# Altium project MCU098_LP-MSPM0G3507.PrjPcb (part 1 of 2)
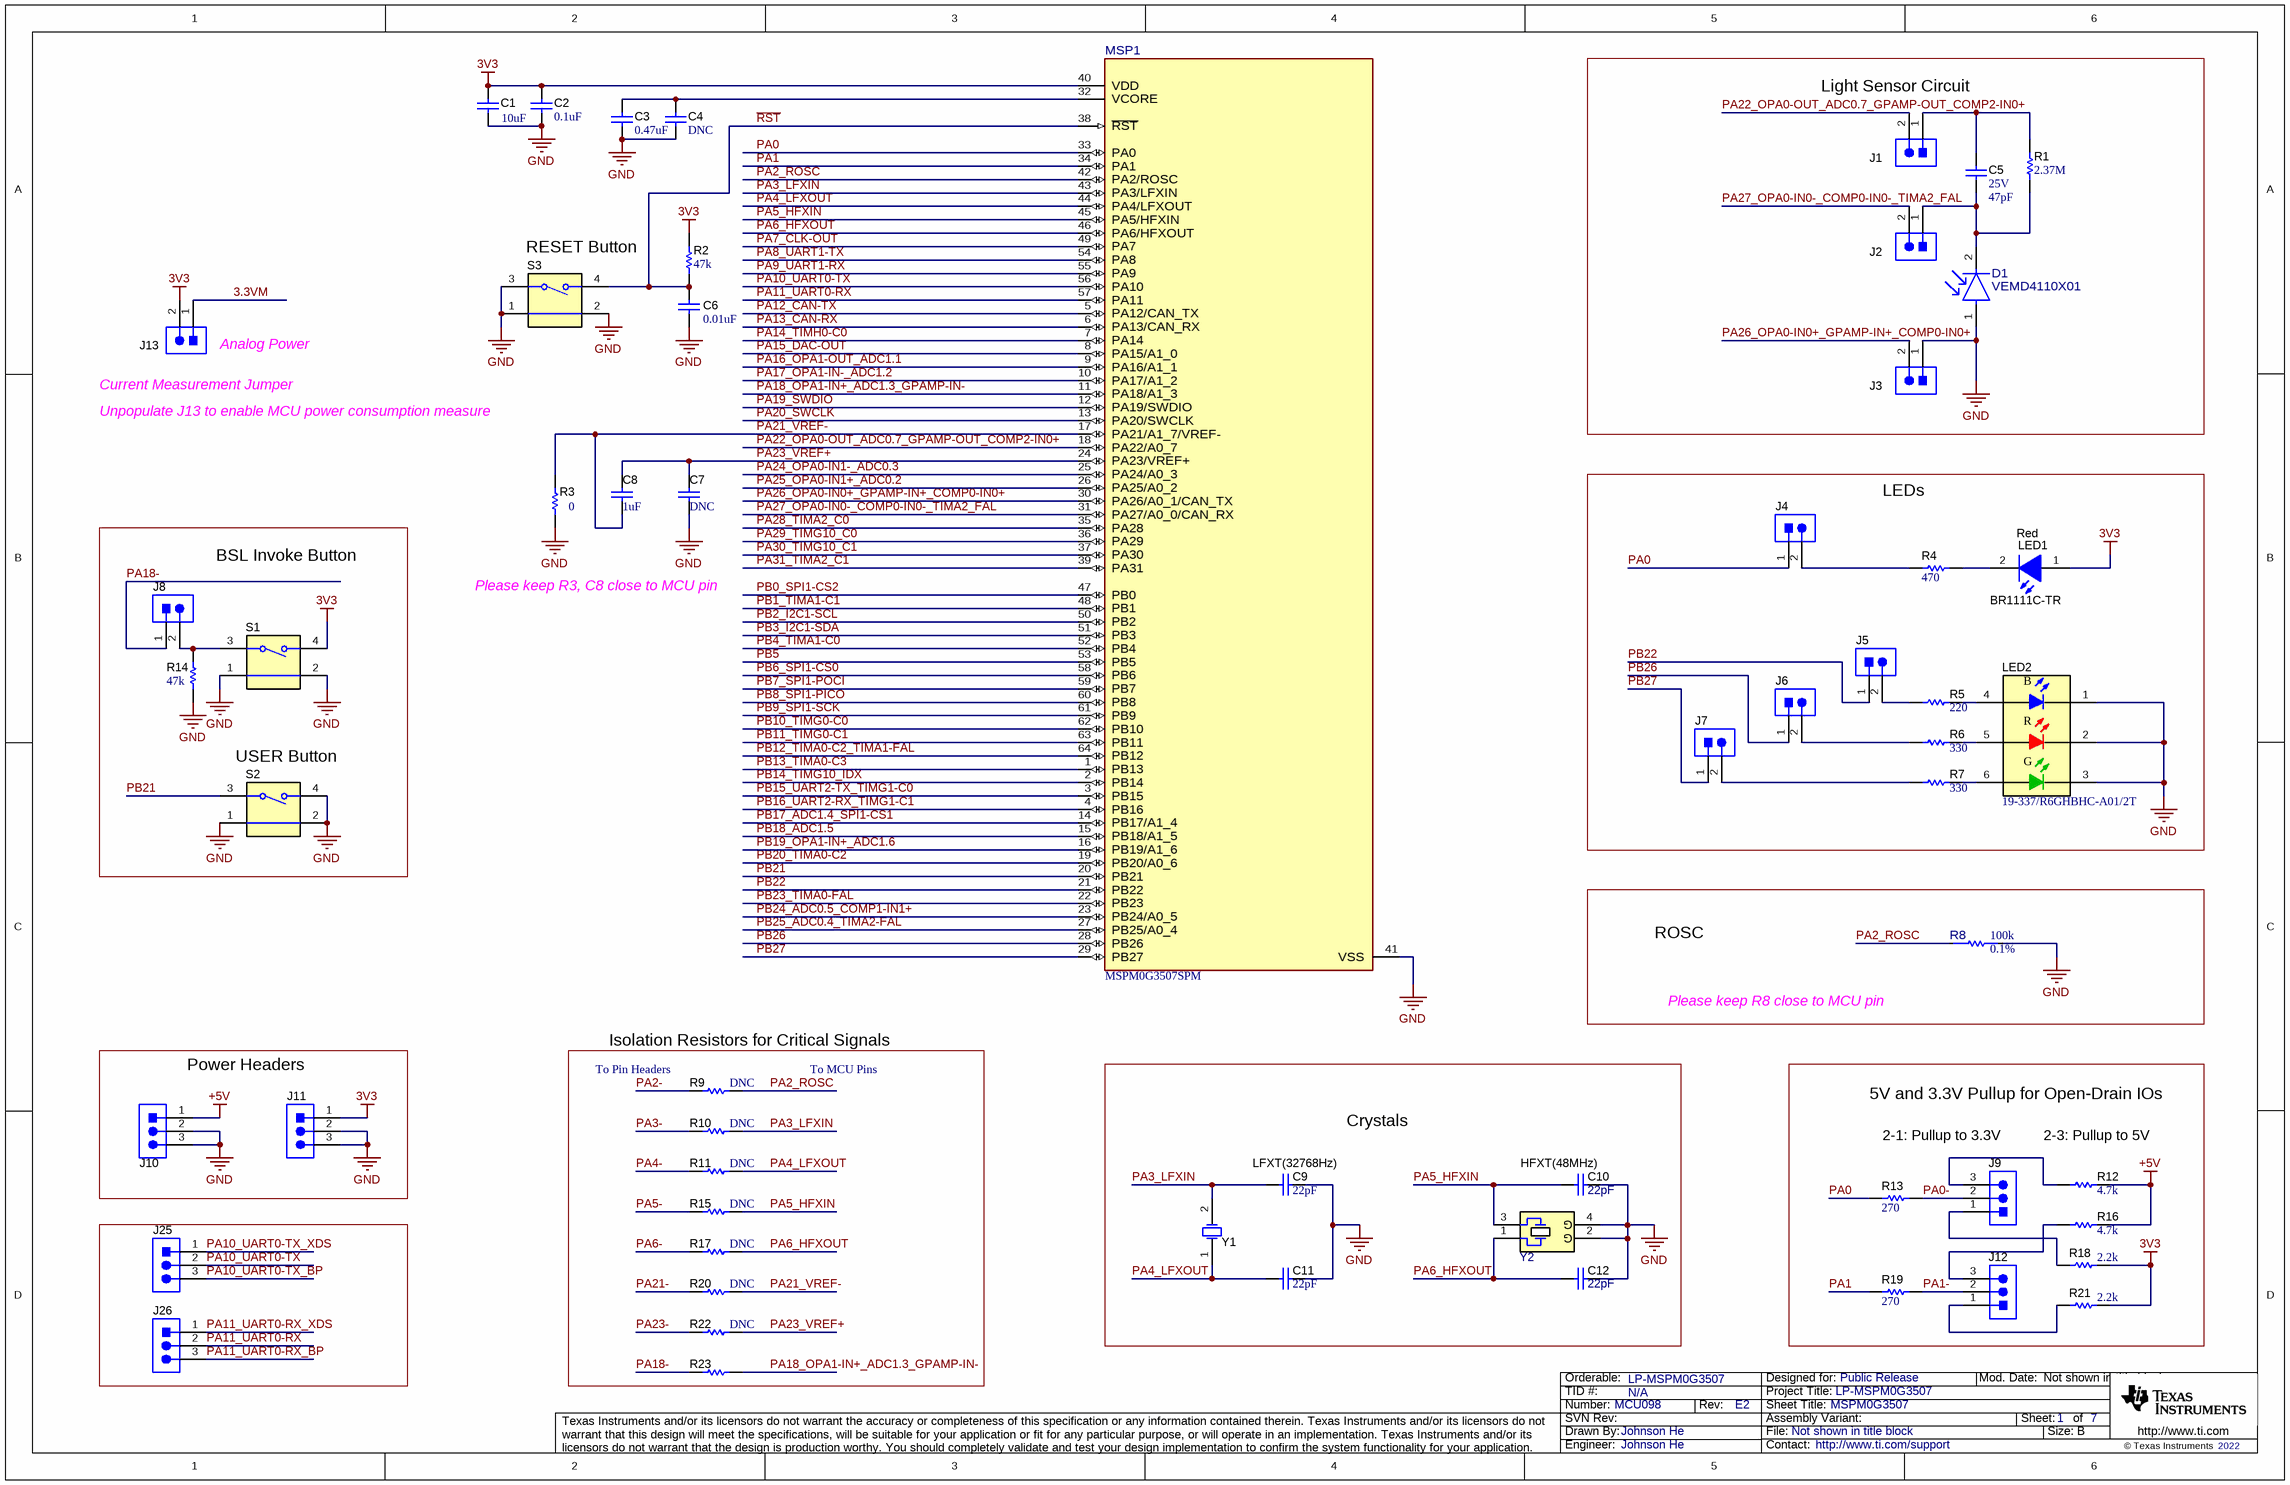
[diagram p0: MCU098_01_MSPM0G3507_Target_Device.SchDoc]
CopyrightYear: 2022; EVM_orderable: LP-MSPM0G3507; PCB_Layout: Johnson He; PCB_Rev: E2; PRJ_Customer: Public Release; PRJ_Engineer: Johnson He; PRJ_Number: MCU098; PRJ_Title: LP-MSPM0G3507; SCH_Rev: E2; TechSupport: http://www.ti.com/support; TID: N/A
7 sheets, 263 parts. Net scope: global (net labels, ports and power ports of the same name join across sheets).
Board file: MCU098_MSPM0G3507_PCB.PcbDoc
Sheets:
  MCU098_01_MSPM0G3507_Target_Device.SchDoc
  MCU098_02_BoosterPack_Connectors.SchDoc
  MCU098_03_XDS110_Debug_Probe.SchDoc
  MCU098_04_XDS110-ET_EnergyTrace.SchDoc
  MCU098_05_XDS110_Target_Interface.SchDoc
  MCU098_06_XDS110-ET_USB_Power.SchDoc
  MCU098_07_Hardware.SchDoc

## Sheet MCU098_01_MSPM0G3507_Target_Device.SchDoc: MSPM0G3507
size 431 x 279 mm; Date: Not shown in title block; ApprovedBy: Not shown in title block; CheckedBy: Not shown in title block; Author: Not shown in title block; CompanyName: Not shown in title block; DrawnBy: Johnson He; Engineer: Not shown in title block; Organization: Not shown in title block; Address1: Not shown in title block; Address2: Not shown in title block; Address3: Not shown in title block; Address4: Not shown in title block; DocumentNumber: 1; Revision: Use project parameter SCH_Rev; SheetNumber: 1; SheetTotal: 7; PageSetup: Record=PageOptions¦CenterHorizontal=True¦CenterVertical=True¦PrintScale=1.00¦XCorrection=1.00¦YCorrection=1.00¦PrintKind=0¦BorderSize=5000000¦LeftOffset=0¦BottomOffset=0¦Orientation=2¦PaperLength=1000¦PaperWidth=1000¦Scale=100¦PaperSource=15¦PrintQuality=600¦MediaType=1¦DitherType=10¦PaperKind=Letter¦PrintScaleMode=1

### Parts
C1  ValueDisplayed: 10uF  [0603]  (hidden comment: GRM188R60J106ME84)
C2  ValueDisplayed: 0.1uF  [0402]  (hidden comment: GRM155R61H104ME14D)
C3  ValueDisplayed: 0.47uF  [0402]  (hidden comment: GRM155R60J474KE19D)
C4  ValueDisplayed: DNC  [0402]  (hidden comment: GRM155R61H104ME14D)  (no BOM)
C5  VDC_V: 25V  ValueDisplayed: 47pF  [0402]  (hidden comment: GRM1555C1E470JA01D)
C6  ValueDisplayed: 0.01uF  [0402]  (hidden comment: GRM155R61C103KA01D)
C7  ValueDisplayed: DNC  [0603]  (hidden comment: C1608X5R1E105K080AC)  (no BOM)
C8  value 1uF  [0603]  (hidden comment: C1608X5R1E105K080AC)
C9  ValueDisplayed: 22pF  [0402]  (hidden comment: GRM1555C1H220JA01D)
C10  ValueDisplayed: 22pF  [0402]  (hidden comment: GRM1555C1H220JA01D)
C11  ValueDisplayed: 22pF  [0402]  (hidden comment: GRM1555C1H220JA01D)
C12  ValueDisplayed: 22pF  [0402]  (hidden comment: GRM1555C1H220JA01D)
D1  VEMD4110X01  [FP-VEMD4110X01_0805-MFG]
J1  90120-0122  [CONN_90120-0122]  (value not drawn)
J2  90120-0122  [CONN_90120-0122]  (value not drawn)
J3  90120-0122  [CONN_90120-0122]  (value not drawn)
J4  90120-0122  [CONN_90120-0122]  (value not drawn)
J5  90120-0122  [CONN_90120-0122]  (value not drawn)
J6  90120-0122  [CONN_90120-0122]  (value not drawn)
J7  90120-0122  [CONN_90120-0122]  (value not drawn)
J8  90120-0122  [CONN_90120-0122]  (value not drawn)
J9  PEC03SAAN  [CONN_PEC03SAAN]  (value not drawn)
J10  PEC03SAAN  [PEC03SAAN_Launchpad_5V0]  (value not drawn)
J11  PEC03SAAN  [PEC03SAAN_Launchpad_3V3]  (value not drawn)
J12  PEC03SAAN  [CONN_PEC03SAAN]  (value not drawn)
J13  90120-0122  [CONN_90120-0122]  (value not drawn)
J25  PEC03SAAN  [CONN_PEC03SAAN]  (value not drawn)
J26  PEC03SAAN  [CONN_PEC03SAAN]  (value not drawn)
LED1  BR1111C-TR  value Red  [1111C_Red]
LED2  19-337/R6GHBHC-A01/2T  [19-337_RGB]
MSP1  MSPM0G3507SPM  [PM0064A-MFG]
R1  ValueDisplayed: 2.37M  [0603]  (hidden comment: CRCW06032M37FKEA)
R2  ValueDisplayed: 47k  [0402]  (hidden comment: CRCW040247K0JNED)
R3  value 0  [0603]  (hidden comment: RC0603JR-070RL)
R4  ValueDisplayed: 470  [0402]  (hidden comment: CRCW0402470RJNED)
R5  ValueDisplayed: 220  [0402]  (hidden comment: CRCW0402220RJNED)
R6  ValueDisplayed: 330  [0402]  (hidden comment: CRCW0402330RJNED)
R7  ValueDisplayed: 330  [0402]  (hidden comment: CRCW0402330RJNED)
R8  Tolerance_%: 0.1%  Res_ohm: 100k  [FP-ERA-2AEB104X_0402-MFG]  (hidden comment: ERA-2AEB104X)
R9  ValueDisplayed: DNC  [0402]  (hidden comment: RC0402JR-070RL)  (no BOM)
R10  ValueDisplayed: DNC  [0402]  (hidden comment: RC0402JR-070RL)  (no BOM)
R11  ValueDisplayed: DNC  [0402]  (hidden comment: RC0402JR-070RL)  (no BOM)
R12  ValueDisplayed: 4.7k  [0603]  (hidden comment: RC0603JR-074K7L)
R13  ValueDisplayed: 270  [0402]  (hidden comment: CRCW0402270RJNED)
R14  ValueDisplayed: 47k  [0402]  (hidden comment: CRCW040247K0JNED)
R15  ValueDisplayed: DNC  [0402]  (hidden comment: RC0402JR-070RL)  (no BOM)
R16  ValueDisplayed: 4.7k  [0603]  (hidden comment: RC0603JR-074K7L)
R17  ValueDisplayed: DNC  [0402]  (hidden comment: RC0402JR-070RL)  (no BOM)
R18  ValueDisplayed: 2.2k  [0603]  (hidden comment: RC0603JR-0710KL)
R19  ValueDisplayed: 270  [0402]  (hidden comment: CRCW0402270RJNED)
R20  ValueDisplayed: DNC  [0402]  (hidden comment: RC0402JR-070RL)  (no BOM)
R21  ValueDisplayed: 2.2k  [0603]  (hidden comment: RC0603JR-0710KL)
R22  ValueDisplayed: DNC  [0402]  (hidden comment: RC0402JR-070RL)  (no BOM)
R23  RC0402JR-070RL  [0402]  (value not drawn)
S1  1188E-1K2-V-TR  [SW_1188E]  (value not drawn)
S2  1188E-1K2-V-TR  [SW_1188E]  (value not drawn)
S3  1188E-1K2-V-TR  [SW_1188E]  (value not drawn)
Y1  X1A0001410014  [Epson_FC-135]  (value not drawn)
Y2  FA-238 48.0000MB-W0  [Epson_FA-238]  (value not drawn)

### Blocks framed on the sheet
Light Sensor Circuit: C5 D1 J1-J3 R1
LEDs: J4-J7 LED1 LED2 R4-R7
ROSC: R8
Power Headers: J10 J11
Isolation Resistors for Critical Signals: R9-R11 R15 R17 R20 R22 R23
Crystals: C9-C12 Y1 Y2
5V and 3.3V Pullup for Open-Drain IOs: J9 J12 R12 R13 R16 R18 R19 R21

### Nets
3V3: C1.1 C2.1 J11.1 J13.2 LED1.1(A) MSP1.40(VDD) R2.2 R18.2 R21.2 S1.4
+5V: J10.1 R12.2 R16.2
GND: C1.2 C2.2 C3.2 C4.2 C6.2 C7.2 C9.1 C10.1 C11.1 C12.1 D1.1(ANODE) J3.1 J10.2 J10.3 J11.2 J11.3 LED2.1(K) LED2.2(K) LED2.3(K) MSP1.41(VSS) R3.1 R8.2 R14.1 S1.1 S1.2 S2.1 S2.2 S2.4 S3.1 S3.2 S3.3 Y2.2(GND) Y2.4(GND)
3.3VM: J13.1
PA0: J4.1 MSP1.33(PA0) R13.1
PA0-: J9.2 R13.2
PA1: MSP1.34(PA1) R19.1
PA1-: J12.2 R19.2
PA2-: R9.1
PA2_ROSC: MSP1.42(PA2/ROSC) R8.1 R9.2
PA3-: R10.1
PA3_LFXIN: C9.2 MSP1.43(PA3/LFXIN) R10.2 Y1.2(OSC2)
PA4-: R11.1
PA4_LFXOUT: C11.2 MSP1.44(PA4/LFXOUT) R11.2 Y1.1(OSC1)
PA5-: R15.1
PA5_HFXIN: C10.2 MSP1.45(PA5/HFXIN) R15.2 Y2.3
PA6-: R17.1
PA6_HFXOUT: C12.2 MSP1.46(PA6/HFXOUT) R17.2 Y2.1
PA7_CLK-OUT: MSP1.49(PA7)
PA8_UART1-TX: MSP1.54(PA8)
PA9_UART1-RX: MSP1.55(PA9)
PA10_UART0-TX: J25.2 MSP1.56(PA10)
PA10_UART0-TX_BP: J25.3
PA10_UART0-TX_XDS: J25.1
PA11_UART0-RX: J26.2 MSP1.57(PA11)
PA11_UART0-RX_BP: J26.3
PA11_UART0-RX_XDS: J26.1
PA12_CAN-TX: MSP1.5(PA12/CAN_TX)
PA13_CAN-RX: MSP1.6(PA13/CAN_RX)
PA14_TIMH0-C0: MSP1.7(PA14)
PA15_DAC-OUT: MSP1.8(PA15/A1_0)
PA16_OPA1-OUT_ADC1.1: MSP1.9(PA16/A1_1)
PA17_OPA1-IN-_ADC1.2: MSP1.10(PA17/A1_2)
PA18-: J8.1 R23.1
PA18_OPA1-IN+_ADC1.3_GPAMP-IN-: MSP1.11(PA18/A1_3) R23.2
PA19_SWDIO: MSP1.12(PA19/SWDIO)
PA20_SWCLK: MSP1.13(PA20/SWCLK)
PA21-: R20.1
PA21_VREF-: C8.2 MSP1.17(PA21/A1_7/VREF-) R3.2 R20.2
PA22_OPA0-OUT_ADC0.7_GPAMP-OUT_COMP2-IN0+: J1.2 MSP1.18(PA22/A0_7)
PA23-: R22.1
PA23_VREF+: C7.1 C8.1 MSP1.24(PA23/VREF+) R22.2
PA24_OPA0-IN1-_ADC0.3: MSP1.25(PA24/A0_3)
PA25_OPA0-IN1+_ADC0.2: MSP1.26(PA25/A0_2)
PA26_OPA0-IN0+_GPAMP-IN+_COMP0-IN0+: J3.2 MSP1.30(PA26/A0_1/CAN_TX)
PA27_OPA0-IN0-_COMP0-IN0-_TIMA2_FAL: J2.2 MSP1.31(PA27/A0_0/CAN_RX)
PA28_TIMA2_C0: MSP1.35(PA28)
PA29_TIMG10_C0: MSP1.36(PA29)
PA30_TIMG10_C1: MSP1.37(PA30)
PA31_TIMA2_C1: MSP1.39(PA31)
PB0_SPI1-CS2: MSP1.47(PB0)
PB1_TIMA1-C1: MSP1.48(PB1)
PB2_I2C1-SCL: MSP1.50(PB2)
PB3_I2C1-SDA: MSP1.51(PB3)
PB4_TIMA1-C0: MSP1.52(PB4)
PB5: MSP1.53(PB5)
PB6_SPI1-CS0: MSP1.58(PB6)
PB7_SPI1-POCI: MSP1.59(PB7)
PB8_SPI1-PICO: MSP1.60(PB8)
PB9_SPI1-SCK: MSP1.61(PB9)
PB10_TIMG0-C0: MSP1.62(PB10)
PB11_TIMG0-C1: MSP1.63(PB11)
PB12_TIMA0-C2_TIMA1-FAL: MSP1.64(PB12)
PB13_TIMA0-C3: MSP1.1(PB13)
PB14_TIMG10_IDX: MSP1.2(PB14)
PB15_UART2-TX_TIMG1-C0: MSP1.3(PB15)
PB16_UART2-RX_TIMG1-C1: MSP1.4(PB16)
PB17_ADC1.4_SPI1-CS1: MSP1.14(PB17/A1_4)
PB18_ADC1.5: MSP1.15(PB18/A1_5)
PB19_OPA1-IN+_ADC1.6: MSP1.16(PB19/A1_6)
PB20_TIMA0-C2: MSP1.19(PB20/A0_6)
PB21: MSP1.20(PB21) S2.3
PB22: J5.1 MSP1.21(PB22)
PB23_TIMA0-FAL: MSP1.22(PB23)
PB24_ADC0.5_COMP1-IN1+: MSP1.23(PB24/A0_5)
PB25_ADC0.4_TIMA2-FAL: MSP1.27(PB25/A0_4)
PB26: J6.1 MSP1.28(PB26)
PB27: J7.1 MSP1.29(PB27)
~{RST}: C6.1 MSP1.38(~{RST}) R2.1 S3.4
NetC3_1: C3.1 C4.1 MSP1.32(VCORE)
NetC5_1: C5.1 J1.1 R1.2
NetC5_2: C5.2 D1.2(CATHODE) J2.1 R1.1
NetJ4_2: J4.2 R4.1
NetJ5_2: J5.2 R5.1
NetJ6_2: J6.2 R6.1
NetJ7_2: J7.2 R7.1
NetJ8_2: J8.2 R14.2 S1.3
NetJ9_1: J9.1 R18.1
NetJ9_3: J9.3 R12.1
NetJ12_1: J12.1 R21.1
NetJ12_3: J12.3 R16.1
NetLED1_2: LED1.2(K) R4.2
NetLED2_4: LED2.4(A) R5.2
NetLED2_5: LED2.5(A) R6.2
NetLED2_6: LED2.6(A) R7.2

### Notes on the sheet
- (near S3) RESET Button
- (near J13) Analog Power
- (near J13) Current Measurement Jumper
- Unpopulate J13 to enable MCU power consumption measure
- BSL Invoke Button
- Please keep R3, C8 close to MCU pin
- (near S2) USER Button
- Please keep R8 close to MCU pin
- (near R9) To Pin Headers
- To MCU Pins
- (near C9) LFXT(32768Hz)
- (near C10) HFXT(48MHz)
- 2-1: Pullup to 3.3V
- (near R12) 2-3: Pullup to 5V

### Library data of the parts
C1 = CMP-0007304-1: CAP, CERM, 10 uF, 6.3 V, +/- 20%, X5R, 0603; Manufacturer: MuRata; TaMin_C: -55°C; Polarized: N; SizeAreaWB_mm2: 4.68; Value1: Unknown; U/M: EA; Value: 10uF; TaMax_C: 85°C; SizeZ_mm: 1; SizeX_mm: 1.6; SizeY_mm: 0.8; Value2: 6.3V; SizeArea_mm2: 1.28; Cap_F: 10µF; AEC Category: Q200
C2 C4 = CMP-0006614-2: CAP, CERM, 0.1 uF, 50 V, +/- 20%, X5R, 0402; Manufacturer: MuRata; TaMin_C: -55°C; Polarized: N; SizeAreaWB_mm2: 3; Value1: Unknown; U/M: EA; Value: 0.1uF; TaMax_C: 85°C; SizeZ_mm: 0.6; SizeX_mm: 1; SizeY_mm: 0.5; Value2: 50V; Cap_F: 100nF; AEC Category: Q200
C3 = CMP-0006551-2: CAP, CERM, 0.47 uF, 6.3 V, +/- 10%, X5R, 0402; Manufacturer: MuRata; TaMin_C: -55°C; Polarized: N; SizeAreaWB_mm2: 3; Value1: Unknown; U/M: EA; Value: 0.47uF; TaMax_C: 85°C; SizeZ_mm: 0.6; SizeX_mm: 1; SizeY_mm: 0.5; Value2: 6.3V; Cap_F: 470nF; AEC Category: Q200
C5 = CMP-0006388-2: CAP, CERM, 47 pF, 25 V, +/- 5%, C0G/NP0, 0402; Manufacturer: MuRata; TaMin_C: -55°C; Polarized: N; SizeAreaWB_mm2: 3; Value1: Unknown; U/M: EA; Value: 47pF; TaMax_C: 125°C; SizeZ_mm: 0.6; SizeX_mm: 1; SizeY_mm: 0.5; AEC Category: Q200
C6 = CMP-0006590-2: CAP, CERM, 0.01 uF, 16 V, +/- 10%, X5R, 0402; Manufacturer: MuRata; TaMin_C: -55°C; Polarized: N; SizeAreaWB_mm2: 3; Value1: Unknown; U/M: EA; Value: 0.01uF; TaMax_C: 85°C; SizeZ_mm: 0.6; SizeX_mm: 1; SizeY_mm: 0.5; Value2: 16V; Cap_F: 10nF; AEC Category: Q200
C7 = CMP-0007006-5: CAP, CERM, 1 uF, 25 V, +/- 10%, X5R, 0603; Manufacturer: TDK; TaMin_C: -55°C; Polarized: N; SizeAreaWB_mm2: 4.68; Value1: Unknown; U/M: EA; Value: 1uF; TaMax_C: 85°C; SizeZ_mm: 1; SizeX_mm: 1.6; SizeY_mm: 0.8; Value2: 25V; SizeArea_mm2: 1.28; Cap_F: 1µF; AEC Category: Q200
C8 = CMP-0007006-5: CAP, CERM, 1 uF, 25 V, +/- 10%, X5R, 0603; Manufacturer: TDK; TaMin_C: -55°C; Polarized: N; SizeAreaWB_mm2: 4.68; Value1: Unknown; U/M: EA; TaMax_C: 85°C; SizeZ_mm: 1; SizeX_mm: 1.6; SizeY_mm: 0.8; Value2: 25V; SizeArea_mm2: 1.28; Cap_F: 1µF; AEC Category: Q200; ValueDisplayed: DNC
C9-C12 = CMP-0006439-2: CAP, CERM, 22 pF, 50 V, +/- 5%, C0G/NP0, 0402; Manufacturer: MuRata; TaMin_C: -55°C; Polarized: N; SizeAreaWB_mm2: 3; Value1: Unknown; U/M: EA; Value: 22pF; TaMax_C: 125°C; SizeZ_mm: 0.6; SizeX_mm: 1; SizeY_mm: 0.5; Value2: 50V; AEC Category: Q200
D1 = CMP-0093192-1: Photodiode PIN Chip 910nm Automotive 2-Pin Case 0805(2012Metric) T/R; Manufacturer: Vishay; TaMax_C: +110°C; Reverse Breakdown Voltage: 20V; AEC Qualified: Yes; TaMin_C: -40°C; Angle: 110°; Forward Current: 50mA; Vf_V: 1.1V; AEC Grade: Grade 2; Dark Current: 0.001uA; SizeZ_mm: 0.8mm
J1-J8 J13 = CMP-0055312-1: Header, 100mil, 2x1, Tin, TH; Manufacturer: Molex; CNHeader: TRUE; Green_Lifecycle: Active; Green_REACh: Passed; CT: FALSE
J9-J12 J25 J26 = CMP-0002338-1: Header, 100mil, 3x1, Tin, TH; Manufacturer: Sullins Connector Solutions; CNHeader: TRUE; Current_A: 3A; Green_Lifecycle: Not Set; Shrouded: N; Gender: Male; Green_REACh: Incomplete; Voltage_V: 1.8kV; Row_Count: 1; Pitch_mm: 2.54; CT: FALSE; Cert_UL: Y
LED1 = CMP-0002972-3: LED, Red, SMD; Manufacturer: Stanley Electric Co., LTD; Power_TotalModule: 57.5mW; Vr_V: 4V; Value1: 0.0575W; Ir_A: 100µA; Io_A: 20mA; Value2: 1.7V; Tjmax_C: 85°C
LED2 = CMP-0074720-1: LED, RGB, SMD; Manufacturer: Everlight; Io_A: 25mA; Vr_V: 5V; Tjmax_C: 85°C; Value1: W; U/M: EA; Angle: 120.0; Ir_A: 50µA; Vf_V: 3.8V
MSP1 = CMP-0093960-1: Mixed-Signal Microcontrollers With CAN-FD Interface LQFP64; Manufacturer: Texas Instruments; Number Of I2C Channels: 2; Frequency_Fixed: 80MHz; Number Of Cores: 1; Number Of Pwm Channels: 14; Data Bus Width: 32bits; Standoff Height: 0.05mm; SizeZ_mm: 1.6mm; Number Of I/Os: 60; Memory Type: FLASH; Min Supply Voltage: 1.62V; Number Of Adc Channels: 16; Memory Size: 128KBytes; TJmax_C: +130°C; Number Of Uart Channels: 4; Number Of Timers/Counters: 7; Max Supply Voltage: 3.6V; TaMin_C: -40°C; Core Architecture: ARM Cortex-M0+; Interface: I2C,SPI,UART,CAN,LIN,IrDA,SMBus; Ram Size: 32KBytes; AEC Qualified: No; TaMax_C: +125°C
R1 = CMP-0022292-1: RES, 2.37 M, 1%, 0.1 W, 0603; Manufacturer: Vishay-Dale; Power_W: 100mW; TempCo: 100 ppm/C; Value_Code: 2M37; U/M: EA; Value: 2.37Meg; EIA_Code: E96; SizeX_mm: 1.6; SizeY_mm: 0.8; SizeZ_mm: 1; Value2: 0.1W; SizeArea_mm2: 1.28; VDC_V: 75V; AEC Category: Q200
R2 R14 = CMP-0026935-1: RES, 47 k, 5%, 0.063 W, 0402; Manufacturer: Vishay-Dale; Power_W: 63mW; TempCo: 200 ppm/C; Value_Code: 47k0; U/M: EA; Value: 47k; EIA_Code: E24; SizeX_mm: 1; SizeY_mm: 0.5; SizeZ_mm: 0.6; Value2: 0.063W; VDC_V: 50V; AEC Category: Q200
R3 = CMP-0025885-5: RES, 0, 5%, 0.1 W, 0603; Manufacturer: Yageo; Power_W: 100mW; TempCo: 200 ppm/C; Value_Code: 0000; EIA_Code: E24; SizeX_mm: 1.6; SizeZ_mm: 1; Value2: 0.1W; SizeArea_mm2: 1.28; AEC Qualified: N; VDC_V: 75V; AEC Category: Q200; ValueDisplayed: DNC; SizeY_mm: 0.8; SizeAreaWB_mm2: 4.68
R4 = CMP-0026934-2: RES, 470, 5%, 0.063 W, 0402; Manufacturer: Vishay-Dale; Power_W: 63mW; TempCo: 200 ppm/C; Value_Code: 470R; U/M: EA; Value: 470; EIA_Code: E24; SizeX_mm: 1; SizeY_mm: 0.5; SizeZ_mm: 0.6; Value2: 0.063W; VDC_V: 50V; AEC Category: Q200
R5 = CMP-0026878-1: RES, 220, 5%, 0.063 W, 0402; Manufacturer: Vishay-Dale; Power_W: 63mW; TempCo: 200 ppm/C; Value_Code: 220R; U/M: EA; Value: 220; EIA_Code: E24; SizeX_mm: 1; SizeY_mm: 0.5; SizeZ_mm: 0.6; Value2: 0.063W; VDC_V: 50V; AEC Category: Q200
R6 R7 = CMP-0026906-1: RES, 330, 5%, 0.063 W, 0402; Manufacturer: Vishay-Dale; Power_W: 63mW; TempCo: 200 ppm/C; Value_Code: 330R; U/M: EA; Value: 330; EIA_Code: E24; SizeX_mm: 1; SizeY_mm: 0.5; SizeZ_mm: 0.6; Value2: 0.063W; VDC_V: 50V; AEC Category: Q200
R8 = CMP-0088648-1: Res Thin Film 0402 100K Ohm 0.1% 1/16W ±25ppm/°C Molded SMD SMD Punched Carrier T/R; Manufacturer: Panasonic; Category 7542B8484461Ae85: Passive Components; VDC_V: 50V; Category Cd01000Bfc2916C6: Single Components; Power_W: 63mW; Category 5A00970A6D5C81C7: Uncategorized; AEC Qualified: Yes; SizeZ_mm: 0.4mm; Voltage: 25V; AEC Grade: Grade 0; Category 5C6A91606D4187Ad: Resistors
R9-R11 R15 R17 R20 R22 R23 = CMP-0027004-2: RES, 0, 5%, 0.063 W, 0402; Manufacturer: Yageo America; Power_W: 63mW; TempCo: 200 ppm/C; Value_Code: 0000; U/M: EA; Value: 0; EIA_Code: E24; SizeX_mm: 1; SizeY_mm: 0.5; SizeZ_mm: 0.6; Value2: 0.063W; VDC_V: 50V; AEC Category: Q200
R12 R16 = CMP-0025927-5: RES, 4.7 k, 5%, 0.1 W, 0603; Manufacturer: Yageo; Power_W: 100mW; TempCo: 100 ppm/C; Value_Code: 4k70; Value: 4.7k; EIA_Code: E24; SizeX_mm: 1.6; SizeY_mm: 0.8; SizeZ_mm: 1; Value2: 0.1W; SizeArea_mm2: 1.28; AEC Qualified: N; VDC_V: 75V; AEC Category: Q200; SizeAreaWB_mm2: 4.68
R13 R19 = CMP-0026886-1: RES, 270, 5%, 0.063 W, 0402; Manufacturer: Vishay-Dale; Power_W: 63mW; TempCo: 200 ppm/C; Value_Code: 270R; U/M: EA; Value: 270; EIA_Code: E24; SizeX_mm: 1; SizeY_mm: 0.5; SizeZ_mm: 0.6; Value2: 0.063W; VDC_V: 50V; AEC Category: Q200
R18 R21 = CMP-0025906-5: RES, 2.2 k, 5%, 0.1 W, 0603; PartNumber: RC0603JR-072K2L; Manufacturer: Yageo; Power_W: 100mW; TempCo: 100 ppm/C; Value_Code: 2k20; Value: 2.2k; EIA_Code: E24; SizeX_mm: 1.6; SizeY_mm: 0.8; SizeZ_mm: 1; Value2: 0.1W; SizeArea_mm2: 1.28; VDC_V: 75V; SizeAreaWB_mm2: 4.68; AEC Qualified: N; AEC Category: Q200
S1-S3 = CMP-0002328-1: Switch, SPST, 0.05 A, 12 VDC, SMD; Manufacturer: Diptronics; CurrentRating_mA: 50A; PositionCount: 1; SizeX_mm: 7.8; SizeY_mm: 3.5; SizeArea_mm2: 27.3; VDC_V: 12V; SizeAreaWB_mm2: 53.9
Y1 = CMP-0004693-2: Crystal, 32.768 KHz, 12.5 pF, SMD; Manufacturer: Epson; TaMax_C: 85°C; TaMin_C: -40°C; U/M: EA
Y2 = CMP-0004696-2: Crystal, 48 MHz, 12pF, SMD; Manufacturer: Epson; TaMin_C: -20°C; Frequency Stability: +/-30ppm; SizeAreaWB_mm2: 14.7; U/M: EA; Frequency_Fixed: 48MHz; TaMax_C: 70°C; SizeZ_mm: 0.7; SizeX_mm: 2.5; SizeY_mm: 3.2; SizeArea_mm2: 8

## Sheet MCU098_02_BoosterPack_Connectors.SchDoc: BoosterPack Connectors
size 431 x 279 mm; Date: Not shown in title block; ApprovedBy: Not shown in title block; CheckedBy: Not shown in title block; Author: Not shown in title block; CompanyName: Not shown in title block; DrawnBy: Johnson He; Engineer: Not shown in title block; Organization: Not shown in title block; Address1: Not shown in title block; Address2: Not shown in title block; Address3: Not shown in title block; Address4: Not shown in title block; DocumentNumber: 1; Revision: Use project parameter SCH_Rev; SheetNumber: 2; SheetTotal: 7; PageSetup: Record=PageOptions¦CenterHorizontal=True¦CenterVertical=True¦PrintScale=1.00¦XCorrection=1.00¦YCorrection=1.00¦PrintKind=0¦BorderSize=5000000¦LeftOffset=0¦BottomOffset=0¦Orientation=2¦PaperLength=1000¦PaperWidth=1000¦Scale=100¦PaperSource=15¦PrintQuality=600¦MediaType=1¦DitherType=10¦PaperKind=Letter¦PrintScaleMode=1
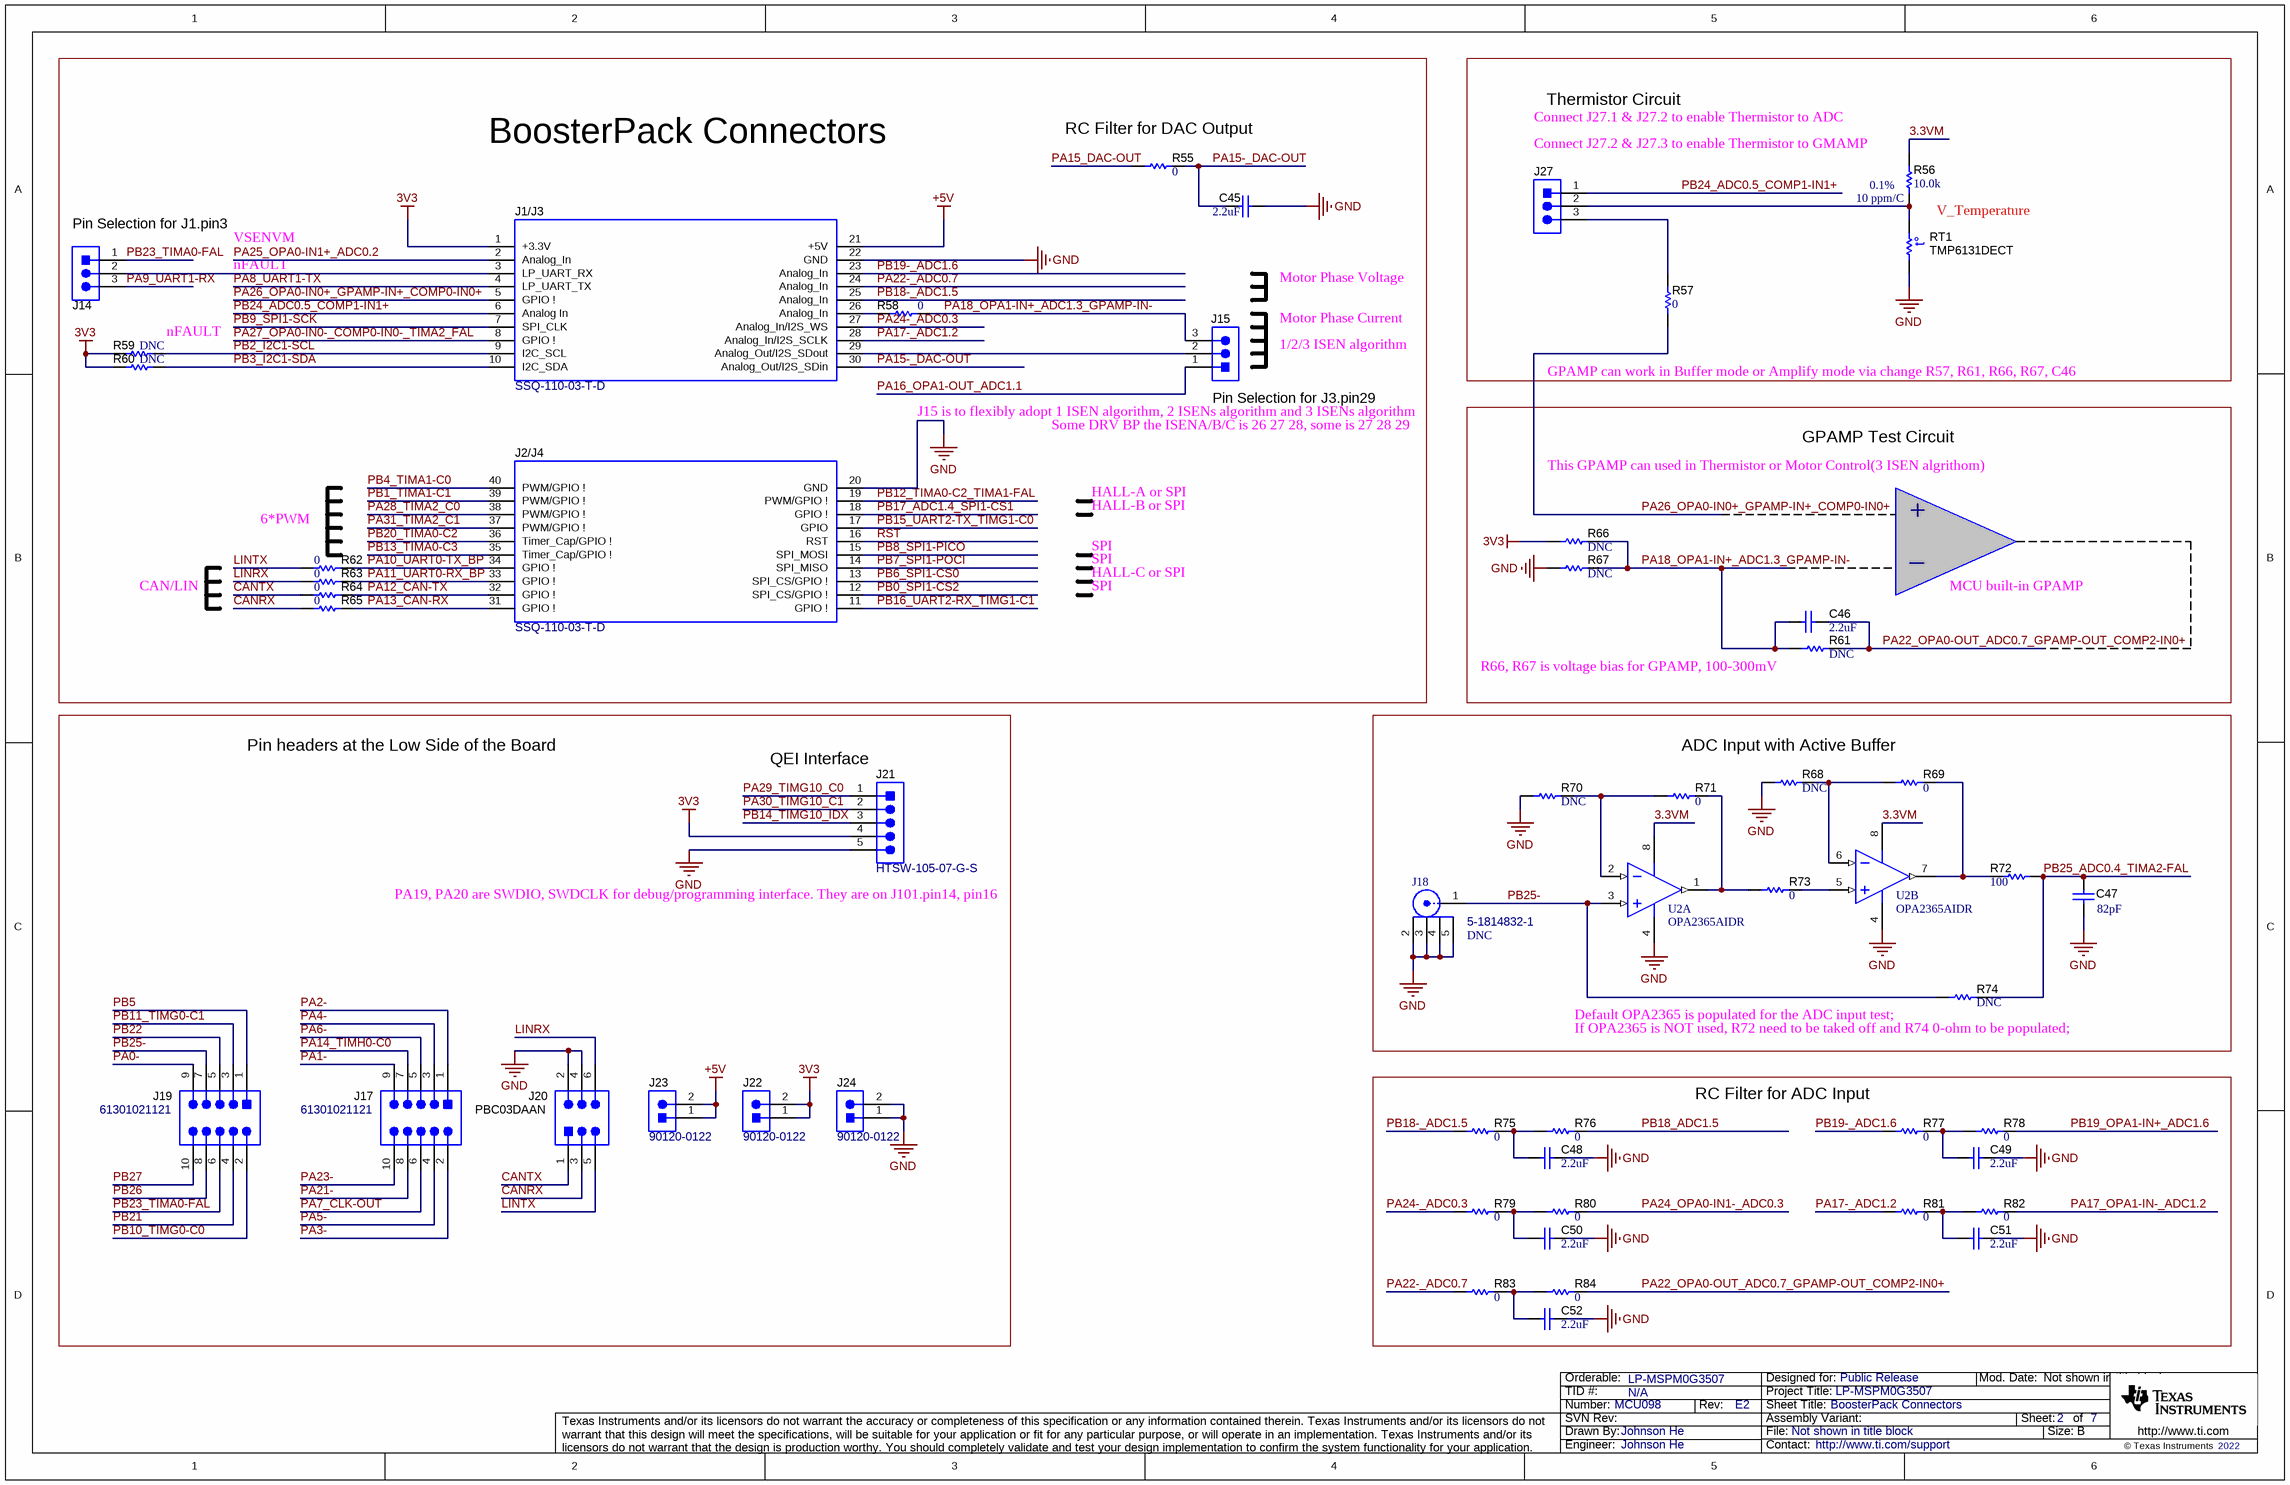
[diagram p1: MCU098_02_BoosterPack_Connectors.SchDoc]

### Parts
(Parts that share a designator on the sheet are numbered #1, #2 ... from top to bottom, then left to right.)
C45  ValueDisplayed: 2.2uF  [0603]  (hidden comment: C0603C225K8PACTU)  (no BOM)
C46  ValueDisplayed: 2.2uF  [0603]  (hidden comment: C0603C225K8PACTU)  (no BOM)
C47  ValueDisplayed: 82pF  [0603]  (hidden comment: C0603C820K5GACTU)
C48  ValueDisplayed: 2.2uF  [0603]  (hidden comment: C0603C225K8PACTU)  (no BOM)
C49  ValueDisplayed: 2.2uF  [0603]  (hidden comment: C0603C225K8PACTU)  (no BOM)
C50  ValueDisplayed: 2.2uF  [0603]  (hidden comment: C0603C225K8PACTU)  (no BOM)
C51  ValueDisplayed: 2.2uF  [0603]  (hidden comment: C0603C225K8PACTU)  (no BOM)
C52  ValueDisplayed: 2.2uF  [0603]  (hidden comment: C0603C225K8PACTU)  (no BOM)
J1/J3  SSQ-110-03-T-D  [BoosterPack_40pin_J1J3]
J2/J4  SSQ-110-03-T-D  [BoosterPack_40pin_J2J4]
J14  PEC03SAAN  [CONN_PEC03SAAN]  (value not drawn)
J15  PEC03SAAN  [CONN_PEC03SAAN]  (value not drawn)
J17  61301021121  [WURTH_61301021121]  (no BOM)
J18  5-1814832-1  ValueDisplayed: DNC  [TE_5-1814832-1]  (no BOM)
J19  61301021121  [WURTH_61301021121]  (no BOM)
J20  PBC03DAAN  [Sullins_PBC03DAAN]  (no BOM)
J21  HTSW-105-07-G-S  [Samtec_HTSW-105-07-G-S]  (net tie, no BOM)
J22  90120-0122  [CONN_90120-0122]  (no BOM)
J23  90120-0122  [CONN_90120-0122]  (no BOM)
J24  90120-0122  [CONN_90120-0122]  (no BOM)
J27  PEC03SAAN  [CONN_PEC03SAAN]  (value not drawn)
R55  ValueDisplayed: 0  [0603]  (hidden comment: RC0603JR-070RL)
R56  Tolerance_%: 0.1%  TempCo: 10 ppm/C  ValueDisplayed: 10.0k  [ERA3A]  (hidden comment: ERA3ARB103V)
R57  ValueDisplayed: 0  [0603]  (hidden comment: RC0603JR-070RL)
R58  ValueDisplayed: 0  [0603]  (hidden comment: RC0603JR-070RL)
R59  ValueDisplayed: DNC  [0402]  (hidden comment: CRCW04024K70JNED)  (no BOM)
R60  ValueDisplayed: DNC  [0402]  (hidden comment: CRCW04024K70JNED)  (no BOM)
R61  ValueDisplayed: DNC  [0603]  (hidden comment: RC0603JR-070RL)  (no BOM)
R62  ValueDisplayed: 0  [0603]  (hidden comment: RC0603JR-070RL)
R63  ValueDisplayed: 0  [0603]  (hidden comment: RC0603JR-070RL)
R64  ValueDisplayed: 0  [0603]  (hidden comment: RC0603JR-070RL)
R65  ValueDisplayed: 0  [0603]  (hidden comment: RC0603JR-070RL)
R66  ValueDisplayed: DNC  [0603]  (hidden comment: RC0603JR-070RL)  (no BOM)
R67  ValueDisplayed: DNC  [0603]  (hidden comment: RC0603JR-070RL)  (no BOM)
R68  ValueDisplayed: DNC  [0603]  (hidden comment: RC0603JR-070RL)  (no BOM)
R69  ValueDisplayed: 0  [0603]  (hidden comment: RC0603JR-070RL)
R70  ValueDisplayed: DNC  [0603]  (hidden comment: RC0603JR-070RL)  (no BOM)
R71  ValueDisplayed: 0  [0603]  (hidden comment: RC0603JR-070RL)
R72  ValueDisplayed: 100  [0603]  (hidden comment: RC0603FR-07100RL)
R73  ValueDisplayed: 0  [0603]  (hidden comment: RC0603JR-070RL)
R74  ValueDisplayed: DNC  [0603]  (hidden comment: RC0603JR-070RL)  (no BOM)
R75  ValueDisplayed: 0  [0603]  (hidden comment: RC0603JR-070RL)
R76  ValueDisplayed: 0  [0603]  (hidden comment: RC0603JR-070RL)
R77  ValueDisplayed: 0  [0603]  (hidden comment: RC0603JR-070RL)
R78  ValueDisplayed: 0  [0603]  (hidden comment: RC0603JR-070RL)
R79  ValueDisplayed: 0  [0603]  (hidden comment: RC0603JR-070RL)
R80  ValueDisplayed: 0  [0603]  (hidden comment: RC0603JR-070RL)
R81  ValueDisplayed: 0  [0603]  (hidden comment: RC0603JR-070RL)
R82  ValueDisplayed: 0  [0603]  (hidden comment: RC0603JR-070RL)
R83  ValueDisplayed: 0  [0603]  (hidden comment: RC0603JR-070RL)
R84  ValueDisplayed: 0  [0603]  (hidden comment: RC0603JR-070RL)
RT1  TMP6131DECT  [DEC0002A]
U2#1  OPA2365AIDR  [D0008A_L]  (parts A,B of 2)

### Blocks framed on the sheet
BoosterPack Connectors: C45 J1/J3 J2/J4 J14 J15 R55 R58-R60 R62-R65
Thermistor Circuit: J27 R56 R57 RT1
ADC Input with Active Buffer: C47 J18 R68-R74 U2#1
RC Filter for ADC Input: C48-C52 R75-R84

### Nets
3V3: J1/J3.1(+3.3V) J21.4 J22.1 J22.2 R59.1 R60.1 R66.1
+5V: J1/J3.21(+5V) J23.1 J23.2
GND: C45.2 C47.2 C48.2 C49.2 C50.2 C51.2 C52.2 J1/J3.22(GND) J2/J4.20(GND) J18.2 J18.3 J18.4 J18.5 J20.2 J20.4 J21.5 J24.1 J24.2 R67.1 R68.1 R70.1 RT1.1 U2#1.4(V-)
3.3VM: R56.2 U2#1.8(V+)
CANRX: J20.3 R65.1
CANTX: J20.1 R64.1
LINRX: J20.6 R63.1
LINTX: J20.5 R62.1
PA0-: J19.9
PA1-: J17.9
PA2-: J17.1
PA3-: J17.2
PA4-: J17.3
PA5-: J17.4
PA6-: J17.5
PA7_CLK-OUT: J17.6
PA8_UART1-TX: J1/J3.4(LP_UART_TX)
PA9_UART1-RX: J14.3
PA10_UART0-TX_BP: J2/J4.34(GPIO_!) R62.2
PA11_UART0-RX_BP: J2/J4.33(GPIO_!) R63.2
PA12_CAN-TX: J2/J4.32(GPIO_!) R64.2
PA13_CAN-RX: J2/J4.31(GPIO_!) R65.2
PA14_TIMH0-C0: J17.7
PA15-_DAC-OUT: C45.1 J1/J3.30(Analog_Out/I2S_SDin) R55.2
PA15_DAC-OUT: R55.1
PA16_OPA1-OUT_ADC1.1: J15.1
PA17-_ADC1.2: J1/J3.28(Analog_In/I2S_SCLK) R81.1
PA17_OPA1-IN-_ADC1.2: R82.2
PA18_OPA1-IN+_ADC1.3_GPAMP-IN-: C46.1 J15.3 R58.2 R61.1 R66.2 R67.2
PA21-: J17.8
PA22-_ADC0.7: J1/J3.24(Analog_In) R83.1
PA22_OPA0-OUT_ADC0.7_GPAMP-OUT_COMP2-IN0+: C46.2 R61.2 R84.2
PA23-: J17.10
PA24-_ADC0.3: J1/J3.27(Analog_In/I2S_WS) R79.1
PA24_OPA0-IN1-_ADC0.3: R80.2
PA25_OPA0-IN1+_ADC0.2: J1/J3.2(Analog_In)
PA26_OPA0-IN0+_GPAMP-IN+_COMP0-IN0+: J1/J3.5(GPIO_!) R57.1
PA27_OPA0-IN0-_COMP0-IN0-_TIMA2_FAL: J1/J3.8(GPIO_!)
PA28_TIMA2_C0: J2/J4.38(PWM/GPIO_!)
PA29_TIMG10_C0: J21.1
PA30_TIMG10_C1: J21.2
PA31_TIMA2_C1: J2/J4.37(PWM/GPIO_!)
PB0_SPI1-CS2: J2/J4.12(SPI_CS/GPIO_!)
PB1_TIMA1-C1: J2/J4.39(PWM/GPIO_!)
PB2_I2C1-SCL: J1/J3.9(I2C_SCL) R59.2
PB3_I2C1-SDA: J1/J3.10(I2C_SDA) R60.2
PB4_TIMA1-C0: J2/J4.40(PWM/GPIO_!)
PB5: J19.1
PB6_SPI1-CS0: J2/J4.13(SPI_CS/GPIO_!)
PB7_SPI1-POCI: J2/J4.14(SPI_MISO)
PB8_SPI1-PICO: J2/J4.15(SPI_MOSI)
PB9_SPI1-SCK: J1/J3.7(SPI_CLK)
PB10_TIMG0-C0: J19.2
PB11_TIMG0-C1: J19.3
PB12_TIMA0-C2_TIMA1-FAL: J2/J4.19(PWM/GPIO_!)
PB13_TIMA0-C3: J2/J4.35(Timer_Cap/GPIO_!)
PB14_TIMG10_IDX: J21.3
PB15_UART2-TX_TIMG1-C0: J2/J4.17(GPIO)
PB16_UART2-RX_TIMG1-C1: J2/J4.11(GPIO_!)
PB17_ADC1.4_SPI1-CS1: J2/J4.18(GPIO_!)
PB18-_ADC1.5: J1/J3.25(Analog_In) R75.1
PB18_ADC1.5: R76.2
PB19-_ADC1.6: J1/J3.23(Analog_In) R77.1
PB19_OPA1-IN+_ADC1.6: R78.2
PB20_TIMA0-C2: J2/J4.36(Timer_Cap/GPIO_!)
PB21: J19.4
PB22: J19.5
PB23_TIMA0-FAL: J14.1 J19.6
PB24_ADC0.5_COMP1-IN1+: J1/J3.6(Analog_In) J27.1
PB25-: J18.1 J19.7 R74.1 U2#1.3(IN_A+)
PB25_ADC0.4_TIMA2-FAL: C47.1 R72.2 R74.2
PB26: J19.8
PB27: J19.10
~{RST}: J2/J4.16(RST)
NetC48_1: C48.1 R75.2 R76.1
NetC49_1: C49.1 R77.2 R78.1
NetC50_1: C50.1 R79.2 R80.1
NetC51_1: C51.1 R81.2 R82.1
NetC52_1: C52.1 R83.2 R84.1
NetJ1/J3_3: J1/J3.3(LP_UART_RX) J14.2
NetJ1/J3_26: J1/J3.26(Analog_In) R58.1
NetJ1/J3_29: J1/J3.29(Analog_Out/I2S_SDout) J15.2
NetJ27_2: J27.2 R56.1 RT1.2
NetJ27_3: J27.3 R57.2
NetR68_2: R68.2 R69.1 U2#1.6(IN_B-)
NetR69_2: R69.2 R72.1 U2#1.7(VOUT_B)
NetR70_2: R70.2 R71.1 U2#1.2(IN_A-)
NetR71_2: R71.2 R73.1 U2#1.1(VOUT_A)
NetR73_2: R73.2 U2#1.5(IN_B+)

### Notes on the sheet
- (near R55) RC Filter for DAC Output
- Connect J27.1 & J27.2 to enable Thermistor to ADC
- (near R56) Connect J27.2 & J27.3 to enable Thermistor to GMAMP
- (near J14) Pin Selection for J1.pin3
- V_Temperature
- VSENVM
- nFAULT
- Motor Phase Voltage
- Motor Phase Current
- 1/2/3 ISEN algorithm
- (near J15) J15 is to flexibly adopt 1 ISEN algorithm, 2 ISENs algorithm and 3 ISENs algorithm
- (near J15) Some DRV BP the ISENA/B/C is 26 27 28, some is 27 28 29
- (near J15) Pin Selection for J3.pin29
- (near R57) GPAMP can work in Buffer mode or Amplify mode via change R57, R61, R66, R67, C46
- HALL-A or SPI
- This GPAMP can used in Thermistor or Motor Control(3 ISEN algrithom)
- GPAMP Test Circuit
- 6*PWM
- HALL-B or SPI
- SPI
- _
- +
- CAN/LIN
- HALL-C or SPI
- MCU built-in GPAMP
- (near R61) R66, R67 is voltage bias for GPAMP, 100-300mV
- Pin headers at the Low Side of the Board
- (near J21) QEI Interface
- (near J21) PA19, PA20 are SWDIO, SWDCLK for debug/programming interface. They are on J101.pin14, pin16
- (near R74) Default OPA2365 is populated for the ADC input test;
- (near R74) If OPA2365 is NOT used, R72 need to be taked off and R74 0-ohm to be populated;

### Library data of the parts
C45 C46 C48-C52 = CMP-0006906-5: CAP, CERM, 2.2 uF, 10 V, +/- 10%, X5R, 0603; Manufacturer: Kemet; TaMin_C: -55°C; Polarized: N; SizeAreaWB_mm2: 4.68; Value1: Unknown; U/M: EA; Value: 2.2uF; TaMax_C: 85°C; SizeZ_mm: 1; SizeX_mm: 1.6; SizeY_mm: 0.8; Value2: 10V; SizeArea_mm2: 1.28; Cap_F: 2.2µF; AEC Category: Q200
C47 = CMP-0006970-1: CAP, CERM, 82 pF, 50 V, +/- 10%, C0G/NP0, 0603; Manufacturer: Kemet; TaMin_C: -55°C; Polarized: N; SizeAreaWB_mm2: 4.68; Value1: Unknown; U/M: EA; Value: 82pF; TaMax_C: 125°C; SizeZ_mm: 1; SizeX_mm: 1.6; SizeY_mm: 0.8; Value2: 50V; SizeArea_mm2: 1.28; AEC Category: Q200
J1/J3 = CMP-0003837-4: Receptacle, 2.54mm, 10x2, Tin, TH; Alternate PartNumber: CRD-081413-A-G; Manufacturer: Samtec; Alternate Manufacturer: Major League Electronics; Note: Booster Pack 40 pin J1 and J3; Green_Lifecycle: Active; Green_REACh: Incomplete
J2/J4 = CMP-0078266-4: Receptacle, 2.54mm, 10x2, Tin, TH; Alternate PartNumber: CRD-081413-A-G; Manufacturer: Samtec; Alternate Manufacturer: Major League Electronics; Note: Booster Pack 40 pin J2 and J4; Green_REACh: Incomplete; Green_Lifecycle: Active
J14 J15 J27 = CMP-0002338-1: as J9 on sheet MCU098_01_MSPM0G3507_Target_Device
J17 J19 = CMP-0054806-2: Header, 2.54 mm, 5x2, Gold, TH; Manufacturer: Wurth Elektronik; Green_Lifecycle: Active; Green_REACh: Passed; Cert_UL: Y; Current_A: 3A; Gender: Male; Pitch_mm: 2.54; Row_Count: 2; Shrouded: N; Voltage_V: 250V
J18 = CMP-0054990-1: SMA Straight PCB Socket Die Cast, 50 Ohm, TH; Manufacturer: TE Connectivity; CNHeader: FALSE; Green_Lifecycle: Active; Green_REACh: Passed; CT: TRUE
J20 = CMP-0054565-2: Header, 100mil, 3x2, Gold, TH; Manufacturer: Sullins Connector Solutions; Current_A: 3A; Green_Lifecycle: Active; Shrouded: N; Gender: Male; Green_REACh: Passed; Voltage_V: 1.8kV; Row_Count: 2; RowSpacing_mm: 2.54; Cert_UL: Y
J21 = CMP-0075485-1: Header, 100mil, 5x1, Gold, TH; Manufacturer: Samtec; Green_REACh: Passed; CT: False; Green_Lifecycle: Active; CNHeader: True
J22-J24 = CMP-0055312-1: as J1 on sheet MCU098_01_MSPM0G3507_Target_Device
R55 R57 R58 R61-R71 R73-R84 = CMP-0025885-5: RES, 0, 5%, 0.1 W, 0603; Manufacturer: Yageo; Power_W: 100mW; TempCo: 200 ppm/C; Value_Code: 0000; Value: 0; EIA_Code: E24; SizeX_mm: 1.6; SizeZ_mm: 1; Value2: 0.1W; SizeArea_mm2: 1.28; AEC Qualified: N; VDC_V: 75V; AEC Category: Q200; SizeY_mm: 0.8; SizeAreaWB_mm2: 4.68
R56 = CMP-0080084-1: RES, 10.0 k, 0.1%, 0.1 W, AEC-Q200 Grade 0, 1.6x0.8mm; Manufacturer: Panasonic; Value_Code: 10k0; SizeAreaWB_mm2: 4.68; SizeArea_mm2: 1.28; AEC Qualified: Y; AEC Category: Q200; Res_ohm: 10k; Value: 10.0k; SizeZ_mm: 0.55; AEC Grade: 0; Power_W: 100mW; VDC_V: 150V; SizeY_mm: 0.8; Value2: 0.1W; SizeX_mm: 1.6
R59 R60 = CMP-0026938-5: RES, 4.7 k, 5%, 0.063 W, AEC-Q200 Grade 0, 0402; Manufacturer: Vishay-Dale; Power_W: 63mW; TempCo: 200 ppm/C; Value_Code: 4k70; Value: 4.7k; EIA_Code: E24; SizeX_mm: 1; SizeY_mm: 0.5; SizeZ_mm: 0.6; Value2: 0.063W; AEC Qualified: Y; VDC_V: 50V; AEC Category: Q200; AEC Grade: 0
R72 = CMP-0022736-4: RES, 100, 1%, 0.1 W, 0603; Manufacturer: Yageo; Power_W: 100mW; TempCo: 100 ppm/C; Value_Code: 100R; Value: 100; EIA_Code: E96; SizeX_mm: 1.6; SizeY_mm: 0.8; SizeZ_mm: 1; Value2: 0.1W; SizeArea_mm2: 1.28; AEC Qualified: N; VDC_V: 75V; AEC Category: Q200; SizeAreaWB_mm2: 4.68
RT1 = CMP-0084565-1: Thermistor, DEC0002A (X1SON-2); Alternate Manufacturer: Texas Instruments; Alternate PartNumber: TMP6131DECR; SizeZ_mm: 0.5; CompType: IC; AEC Category: Q200; SizeArea_mm2: 0.6; AEC Qualified: N; SizeX_mm: 1; SizeAreaWB_mm2: 3.2
U2#1 = CMP-0040798-2: 50 MHz, Low-Noise Single-Supply Rail-to-Rail Operational Amplifier, 2.2 to 5.5 V, -40 to 125 degC, 8-pin SOIC (D8), Green (RoHS & no Sb/Br); Manufacturer: Texas Instruments; Sub Family: High Speed Amplifier (>=50MHz), Low Input Bias Current Amp (<=10pA), Low Offset Voltage Amplifier (<=500uV), Low Supply Voltage Amplifier (<=2.7V); Total Supply Voltage(Min)(+5V is 5, +/-5V is 10): 2.2; Slew Rate(Typ)(V/us): 25; Vio (25C)(Max)(mV): 0.2; IIB(Max)(pA): 10; Total Supply Voltage(Max)(+5V is 5, +/-5V is 10): 5.5; Offset Drift(Typ)(uV/C): 1; Iq per channel(Max)(mA): 5; CMRR(Min)(dB): 100; Number of Channels: 2

## Sheet MCU098_03_XDS110_Debug_Probe.SchDoc: XDS110-ET Debug Probe
size 431 x 279 mm; Date: Not shown in title block; ApprovedBy: Not shown in title block; CheckedBy: Not shown in title block; Author: Not shown in title block; CompanyName: Not shown in title block; DrawnBy: Johnson He; Engineer: Not shown in title block; Organization: Not shown in title block; Address1: Not shown in title block; Address2: Not shown in title block; Address3: Not shown in title block; Address4: Not shown in title block; DocumentNumber: 1; Revision: Use project parameter SCH_Rev; SheetNumber: 3; SheetTotal: 7; PageSetup: Record=PageOptions¦CenterHorizontal=True¦CenterVertical=True¦PrintScale=1.00¦XCorrection=1.00¦YCorrection=1.00¦PrintKind=0¦BorderSize=5000000¦LeftOffset=0¦BottomOffset=0¦Orientation=2¦PaperLength=1000¦PaperWidth=1000¦Scale=100¦PaperSource=15¦PrintQuality=600¦MediaType=1¦DitherType=10¦PaperKind=Letter¦PrintScaleMode=1
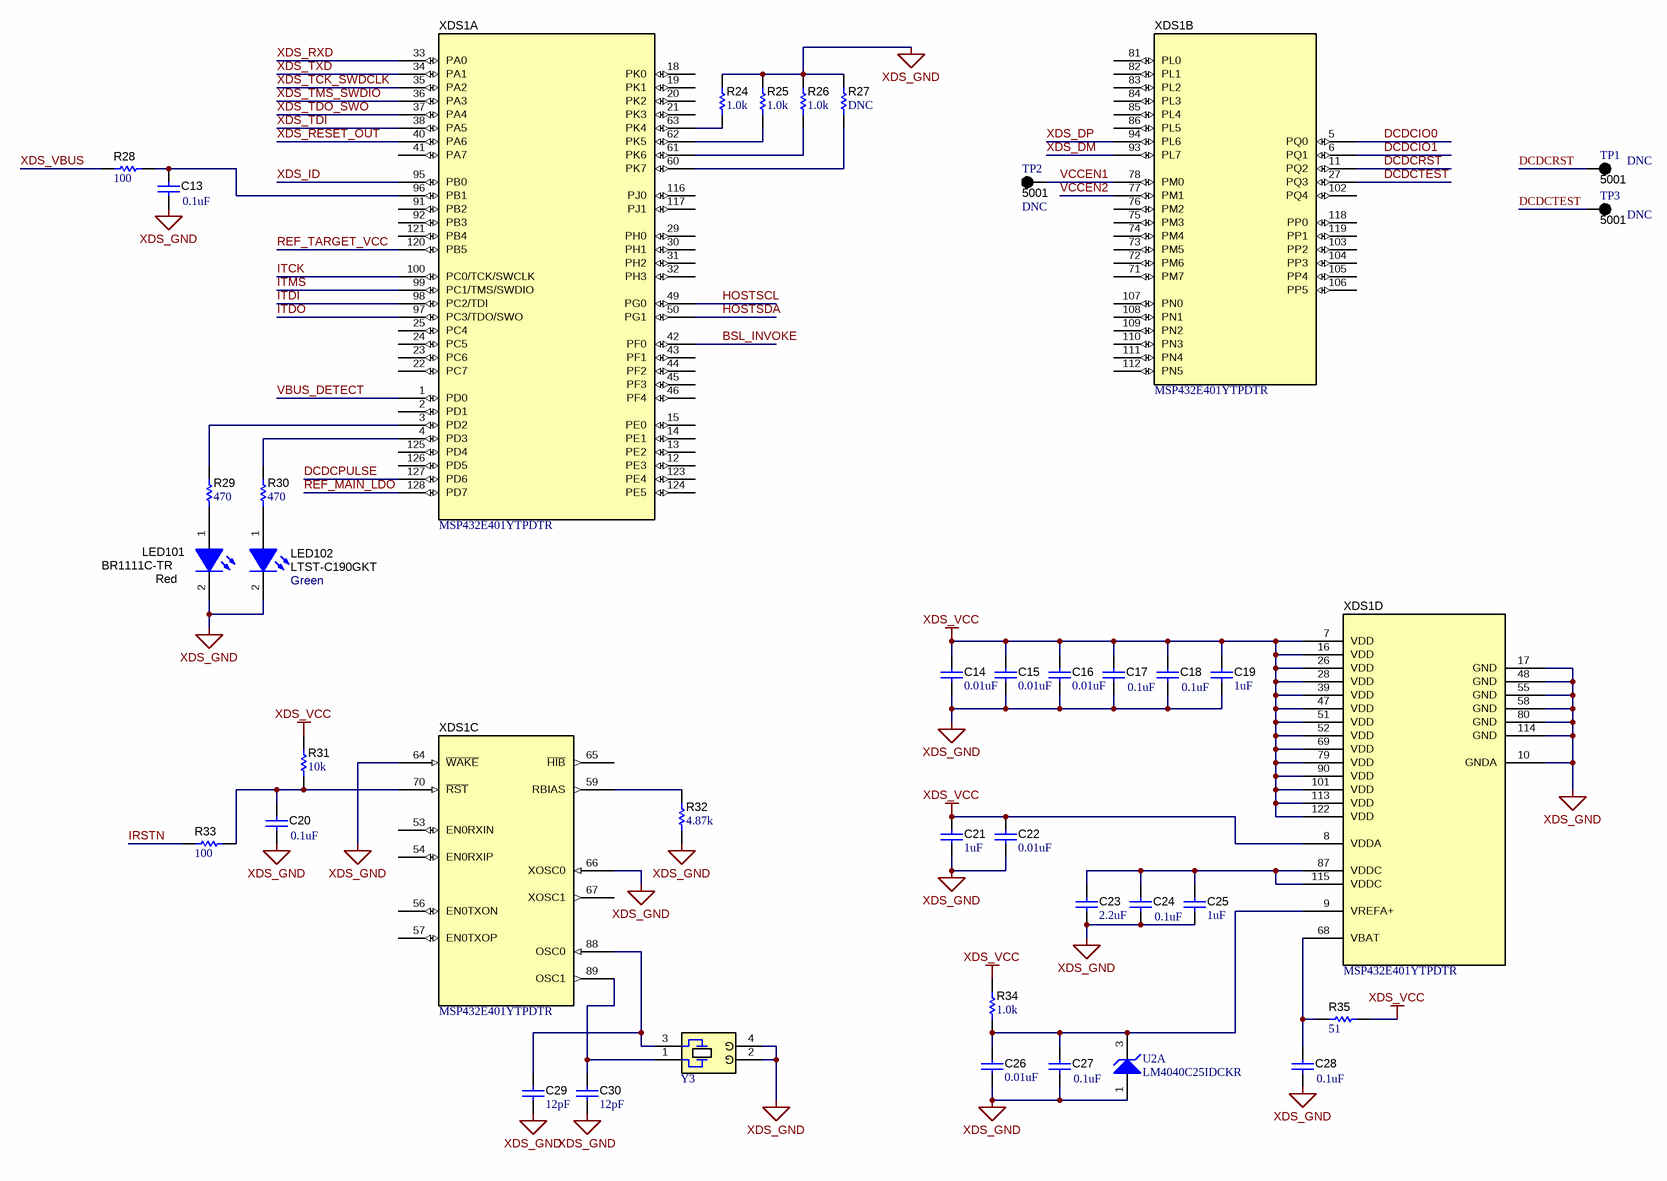
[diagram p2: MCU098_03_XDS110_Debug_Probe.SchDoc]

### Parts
(Parts that share a designator on the sheet are numbered #1, #2 ... from top to bottom, then left to right.)
C13  ValueDisplayed: 0.1uF  [0402]  (hidden comment: GRM155R70J104KA01D)
C14  ValueDisplayed: 0.01uF  [0402]  (hidden comment: GRM155R71E103KA01D)
C15  ValueDisplayed: 0.01uF  [0402]  (hidden comment: GRM155R71E103KA01D)
C16  ValueDisplayed: 0.01uF  [0402]  (hidden comment: GRM155R71E103KA01D)
C17  ValueDisplayed: 0.1uF  [0402]  (hidden comment: GRM155R70J104KA01D)
C18  ValueDisplayed: 0.1uF  [0402]  (hidden comment: GRM155R70J104KA01D)
C19  ValueDisplayed: 1uF  [0402]  (hidden comment: C1005X5R1E105K050BC)
C20  ValueDisplayed: 0.1uF  [0402]  (hidden comment: GRM155R70J104KA01D)
C21  ValueDisplayed: 1uF  [0402]  (hidden comment: C1005X5R1E105K050BC)
C22  ValueDisplayed: 0.01uF  [0402]  (hidden comment: GRM155R71E103KA01D)
C23  ValueDisplayed: 2.2uF  [0402]  (hidden comment: GRM155R60J225KE95D)
C24  ValueDisplayed: 0.1uF  [0402]  (hidden comment: GRM155R70J104KA01D)
C25  ValueDisplayed: 1uF  [0402]  (hidden comment: C1005X5R1E105K050BC)
C26  ValueDisplayed: 0.01uF  [0402]  (hidden comment: GRM155R71E103KA01D)
C27  ValueDisplayed: 0.1uF  [0402]  (hidden comment: GRM155R70J104KA01D)
C28  ValueDisplayed: 0.1uF  [0402]  (hidden comment: GRM155R70J104KA01D)
C29  ValueDisplayed: 12pF  [0402]  (hidden comment: GRM1555C1H120JA01D)
C30  ValueDisplayed: 12pF  [0402]  (hidden comment: GRM1555C1H120JA01D)
LED101  BR1111C-TR  value Red  [1111C_Red]
LED102  LTST-C190GKT  value Green  [LED_LTST-C190]
R24  ValueDisplayed: 1.0k  [0402]  (hidden comment: CRCW04021K00JNED)
R25  ValueDisplayed: 1.0k  [0402]  (hidden comment: CRCW04021K00JNED)
R26  ValueDisplayed: 1.0k  [0402]  (hidden comment: CRCW04021K00JNED)
R27  ValueDisplayed: DNC  [0402]  (hidden comment: CRCW04021K00JNED)  (no BOM)
R28  ValueDisplayed: 100  [0402]  (hidden comment: CRCW0402100RJNED)
R29  ValueDisplayed: 470  [0402]  (hidden comment: CRCW0402470RJNED)
R30  ValueDisplayed: 470  [0402]  (hidden comment: CRCW0402470RJNED)
R31  ValueDisplayed: 10k  [0402]  (hidden comment: CRCW040210K0JNED)
R32  ValueDisplayed: 4.87k  [0402]  (hidden comment: CRCW04024K87FKED)
R33  ValueDisplayed: 100  [0402]  (hidden comment: CRCW0402100RJNED)
R34  ValueDisplayed: 1.0k  [0402]  (hidden comment: CRCW04021K00JNED)
R35  ValueDisplayed: 51  [0402]  (hidden comment: CRCW040251R0JNED)
TP1  5001  Display: DNC  [Keystone5001]  (no BOM)
TP2  5001  Display: DNC  [Keystone5001]  (no BOM)
TP3  5001  Display: DNC  [Keystone5001]  (no BOM)
U2#2  LM4040C25IDCKR  [DCK0005A_N]  (part A of 2)
XDS1  MSP432E401YTPDTR  [PDT0128A]  (parts A,B,C,D of 4)
Y3  NX3225GA-16.000M-STD-CRG-1  [NDK_NX3225GA]  (value not drawn)

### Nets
XDS_GND: C13.2 C14.2 C15.2 C16.2 C17.2 C18.2 C19.2 C20.2 C21.2 C22.2 C23.2 C24.2 C25.2 C26.2 C27.2 C28.2 C29.2 C30.2 LED101.2(K) LED102.2(K) R24.2 R25.2 R26.2 R27.2 R32.1 U2#2.1(ANODE) XDS1.10(GNDA) XDS1.17(GND) XDS1.48(GND) XDS1.55(GND) XDS1.58(GND) XDS1.64(~{WAKE}) XDS1.66(XOSC0) XDS1.80(GND) XDS1.114(GND) Y3.2(GND) Y3.4(GND)
XDS_VCC: C14.1 C15.1 C16.1 C17.1 C18.1 C19.1 C21.1 C22.1 R31.2 R34.2 R35.2 XDS1.7(VDD) XDS1.8(VDDA) XDS1.16(VDD) XDS1.26(VDD) XDS1.28(VDD) XDS1.39(VDD) XDS1.47(VDD) XDS1.51(VDD) XDS1.52(VDD) XDS1.69(VDD) XDS1.79(VDD) XDS1.90(VDD) XDS1.101(VDD) XDS1.113(VDD) XDS1.122(VDD)
BSL_INVOKE: XDS1.42(PF0)
DCDCIO0: XDS1.5(PQ0)
DCDCIO1: XDS1.6(PQ1)
DCDCPULSE: XDS1.127(PD6)
DCDCRST: TP1.1 XDS1.11(PQ2)
DCDCTEST: TP3.1 XDS1.27(PQ3)
HOSTSCL: XDS1.49(PG0)
HOSTSDA: XDS1.50(PG1)
IRSTN: R33.1
ITCK: XDS1.100(PC0/TCK/SWCLK)
ITDI: XDS1.98(PC2/TDI)
ITDO: XDS1.97(PC3/TDO/SWO)
ITMS: XDS1.99(PC1/TMS/SWDIO)
REF_MAIN_LDO: XDS1.128(PD7)
REF_TARGET_VCC: XDS1.120(PB5)
VBUS_DETECT: XDS1.1(PD0)
VCCEN1: TP2.1 XDS1.78(PM0)
VCCEN2: XDS1.77(PM1)
XDS_DM: XDS1.93(PL7)
XDS_DP: XDS1.94(PL6)
XDS_ID: XDS1.95(PB0)
XDS_RESET_OUT: XDS1.40(PA6)
XDS_RXD: XDS1.33(PA0)
XDS_TCK_SWDCLK: XDS1.35(PA2)
XDS_TDI: XDS1.38(PA5)
XDS_TDO_SWO: XDS1.37(PA4)
XDS_TMS_SWDIO: XDS1.36(PA3)
XDS_TXD: XDS1.34(PA1)
XDS_VBUS: R28.1
NetC13_1: C13.1 R28.2 XDS1.96(PB1)
NetC20_1: C20.1 R31.1 R33.2 XDS1.70(~{RST})
NetC23_1: C23.1 C24.1 C25.1 XDS1.87(VDDC) XDS1.115(VDDC)
NetC26_1: C26.1 C27.1 R34.1 U2#2.3(CATHODE) XDS1.9(VREFA+)
NetC28_1: C28.1 R35.1 XDS1.68(VBAT)
NetC29_1: C29.1 XDS1.88(OSC0) Y3.3
NetC30_1: C30.1 XDS1.89(OSC1) Y3.1
NetLED101_1: LED101.1(A) R29.1
NetLED102_1: LED102.1(A) R30.1
NetR24_1: R24.1 XDS1.63(PK4)
NetR25_1: R25.1 XDS1.62(PK5)
NetR26_1: R26.1 XDS1.61(PK6)
NetR27_1: R27.1 XDS1.60(PK7)
NetR29_2: R29.2 XDS1.3(PD2)
NetR30_2: R30.2 XDS1.4(PD3)
NetR32_2: R32.2 XDS1.59(RBIAS)

Not connected (* = marked no-connect by the designer): XDS1 2(PD1) 12(PE3) 13(PE2) 14(PE1) 15(PE0) 18(PK0) 19(PK1) 20(PK2) 21(PK3) 22(PC7) 23(PC6) 24(PC5) 25(PC4) 29(PH0) 30(PH1) 31(PH2) 32(PH3) 41(PA7) 43(PF1) 44(PF2) 45(PF3) 46(PF4) 53(EN0RXIN) 54(EN0RXIP) 56(EN0TXON) 57(EN0TXOP) 65(~{HIB}) 67(XOSC1) 71(PM7) 72(PM6) 73(PM5) 74(PM4) 75(PM3) 76(PM2) 81(PL0) 82(PL1) 83(PL2) 84(PL3) 85(PL4) 86(PL5) 91(PB2) 92(PB3) 102(PQ4) 103(PP2) 104(PP3) 105(PP4) 106(PP5) 107(PN0) 108(PN1) 109(PN2) 110(PN3) 111(PN4) 112(PN5) 116(PJ0) 117(PJ1) 118(PP0) 119(PP1) 121(PB4) 123(PE4) 124(PE5) 125(PD4) 126(PD5)

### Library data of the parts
C13 C17 C18 C20 C24 C27 C28 = CMP-0006623-2: CAP, CERM, 0.1 uF, 6.3 V, +/- 10%, X7R, 0402; Manufacturer: MuRata; TaMin_C: -55°C; Polarized: N; SizeAreaWB_mm2: 3; Value1: Unknown; U/M: EA; Value: 0.1uF; TaMax_C: 125°C; SizeZ_mm: 0.6; SizeX_mm: 1; SizeY_mm: 0.5; Value2: 6.3V; Cap_F: 100nF; AEC Category: Q200
C14-C16 C22 C26 = CMP-0006658-2: CAP, CERM, 0.01 uF, 25 V, +/- 10%, X7R, 0402; Manufacturer: MuRata; TaMin_C: -55°C; Polarized: N; SizeAreaWB_mm2: 3; Value1: Unknown; U/M: EA; Value: 0.01uF; TaMax_C: 125°C; SizeZ_mm: 0.6; SizeX_mm: 1; SizeY_mm: 0.5; Value2: 25V; Cap_F: 10nF; AEC Category: Q200
C19 C21 C25 = CMP-0006276-2: CAP, CERM, 1 uF, 25 V, +/- 10%, X5R, 0402; Manufacturer: TDK; TaMin_C: -55°C; Polarized: N; SizeAreaWB_mm2: 3; Value1: Unknown; U/M: EA; Value: 1uF; TaMax_C: 80°C; SizeZ_mm: 0.6; SizeX_mm: 1; SizeY_mm: 0.5; Value2: 25V; Cap_F: 1µF; AEC Category: Q200
C23 = CMP-0006543-2: CAP, CERM, 2.2 uF, 6.3 V, +/- 10%, X5R, 0402; Manufacturer: MuRata; TaMin_C: -55°C; Polarized: N; SizeAreaWB_mm2: 3; Value1: Unknown; U/M: EA; Value: 2.2uF; TaMax_C: 85°C; SizeZ_mm: 0.6; SizeX_mm: 1; SizeY_mm: 0.5; Value2: 6.3V; Cap_F: 2.2µF; AEC Category: Q200
C29 C30 = CMP-0006415-2: CAP, CERM, 12 pF, 50 V, +/- 5%, C0G/NP0, 0402; Manufacturer: MuRata; TaMin_C: -55°C; Polarized: N; SizeAreaWB_mm2: 3; Value1: Unknown; U/M: EA; Value: 12pF; TaMax_C: 125°C; SizeZ_mm: 0.6; SizeX_mm: 1; SizeY_mm: 0.5; Value2: 50V; AEC Category: Q200
LED101 = CMP-0002972-3: as LED1 on sheet MCU098_01_MSPM0G3507_Target_Device
LED102 = CMP-0002827-3: LED, Green, SMD; Manufacturer: Lite-On; Power_TotalModule: 100mW; Value2: 2.1V; Io_A: 20mA; Value1: 0.1W
R24-R27 R34 = CMP-0026852-1: RES, 1.0 k, 5%, 0.063 W, 0402; Manufacturer: Vishay-Dale; Power_W: 63mW; TempCo: 200 ppm/C; Value_Code: 1k00; U/M: EA; Value: 1.0k; EIA_Code: E24; Res_ohm: 1k; SizeX_mm: 1; SizeY_mm: 0.5; SizeZ_mm: 0.6; Value2: 0.063W; VDC_V: 50V; AEC Category: Q200
R28 = CMP-0026824-3: RES, 100, 5%, 0.063 W, AEC-Q200 Grade 0, 0402; Manufacturer: Vishay-Dale; Power_W: 63mW; TempCo: 200 ppm/C; Value_Code: 100R; Value: 100; EIA_Code: E24; SizeX_mm: 1; SizeY_mm: 0.5; SizeZ_mm: 0.6; Value2: 0.063W; AEC Qualified: Y; VDC_V: 50V; AEC Category: Q200; AEC Grade: 0
R29 R30 = CMP-0026934-2: as R4 on sheet MCU098_01_MSPM0G3507_Target_Device
R31 = CMP-0026825-4: RES, 10 k, 5%, 0.063 W, 0402; Manufacturer: Vishay-Dale; Power_W: 63mW; TempCo: 200 ppm/C; Value_Code: 10k0; U/M: EA; Value: 10k; EIA_Code: E24; SizeX_mm: 1; SizeY_mm: 0.5; SizeZ_mm: 0.6; Value2: 0.063W; VDC_V: 50V; AEC Category: Q200
R32 = CMP-0026413-2: RES, 4.87 k, 1%, 0.063 W, AEC-Q200 Grade 0, 0402; Manufacturer: Vishay-Dale; Power_W: 63mW; TempCo: 100 ppm/C; Value_Code: 4k87; Value: 4.87k; EIA_Code: E96; SizeX_mm: 1; SizeY_mm: 0.5; SizeZ_mm: 0.6; Value2: 0.063W; AEC Qualified: Y; VDC_V: 50V; AEC Category: Q200; AEC Grade: 0
R33 = CMP-0026824-1: RES, 100, 5%, 0.063 W, 0402; Manufacturer: Vishay-Dale; Power_W: 63mW; TempCo: 200 ppm/C; Value_Code: 100R; U/M: EA; Value: 100; EIA_Code: E24; SizeX_mm: 1; SizeY_mm: 0.5; SizeZ_mm: 0.6; Value2: 0.063W; VDC_V: 50V; AEC Category: Q200
R35 = CMP-0026946-3: RES, 51, 5%, 0.063 W, AEC-Q200 Grade 0, 0402; Manufacturer: Vishay-Dale; Power_W: 63mW; TempCo: 200 ppm/C; Value_Code: 51R0; Value: 51; EIA_Code: E24; SizeX_mm: 1; SizeY_mm: 0.5; SizeZ_mm: 0.6; Value2: 0.063W; AEC Qualified: Y; VDC_V: 50V; AEC Category: Q200; AEC Grade: 0
TP1-TP3 = CMP-0055138-1: Test Point, Miniature, Black, TH; Manufacturer: Keystone; CNHeader: FALSE; Green_Lifecycle: Active; Green_REACh: Passed; ContactFinish: Silver; CT: TRUE
U2#2 = CMP-0032790-2: Precision Micropower Shunt Voltage Reference, 0.5% accuracy, 2.5 V, 15 ppm / degC, 15 mA, -40 to 85 degC, 5-pin SC70 (DCK), Green (RoHS & no Sb/Br); Manufacturer: Texas Instruments; Min Iz for Regulation(uA): 75; Temp Coeff(Max)(ppm/ degree C): 100; VO(V): 2.5; Temp Coeff(Typ)(ppm/ degree C): 15; Rating: Catalog; Initial Accuracy @ 25/deg C(%): 0.5; AEC Category: Q200; AEC Qualified: N; CompType: IC; SizeAreaWB_mm2: 9.3; SizeArea_mm2: 4.2; SizeX_mm: 2.1; SizeY_mm: 2.0; SizeZ_mm: 1.1
XDS1 = CMP-0077954-1: MSP432E401YTPDT, PDT0128A (TQFP-128); Alternate Manufacturer: Texas Instruments; SizeAreaWB_mm2: 324; SizeZ_mm: 1.2; SizeX_mm: 16; SizeArea_mm2: 256; CompType: IC; AEC Qualified: N; AEC Category: Q200
Y3 = CMP-0004635-1: Crystal, 16 MHz, 8pF, SMD; Manufacturer: NDK; TaMax_C: 70°C; TaMin_C: -10°C; Frequency Stability: +/-30ppm; U/M: EA; Frequency_Fixed: 16MHz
